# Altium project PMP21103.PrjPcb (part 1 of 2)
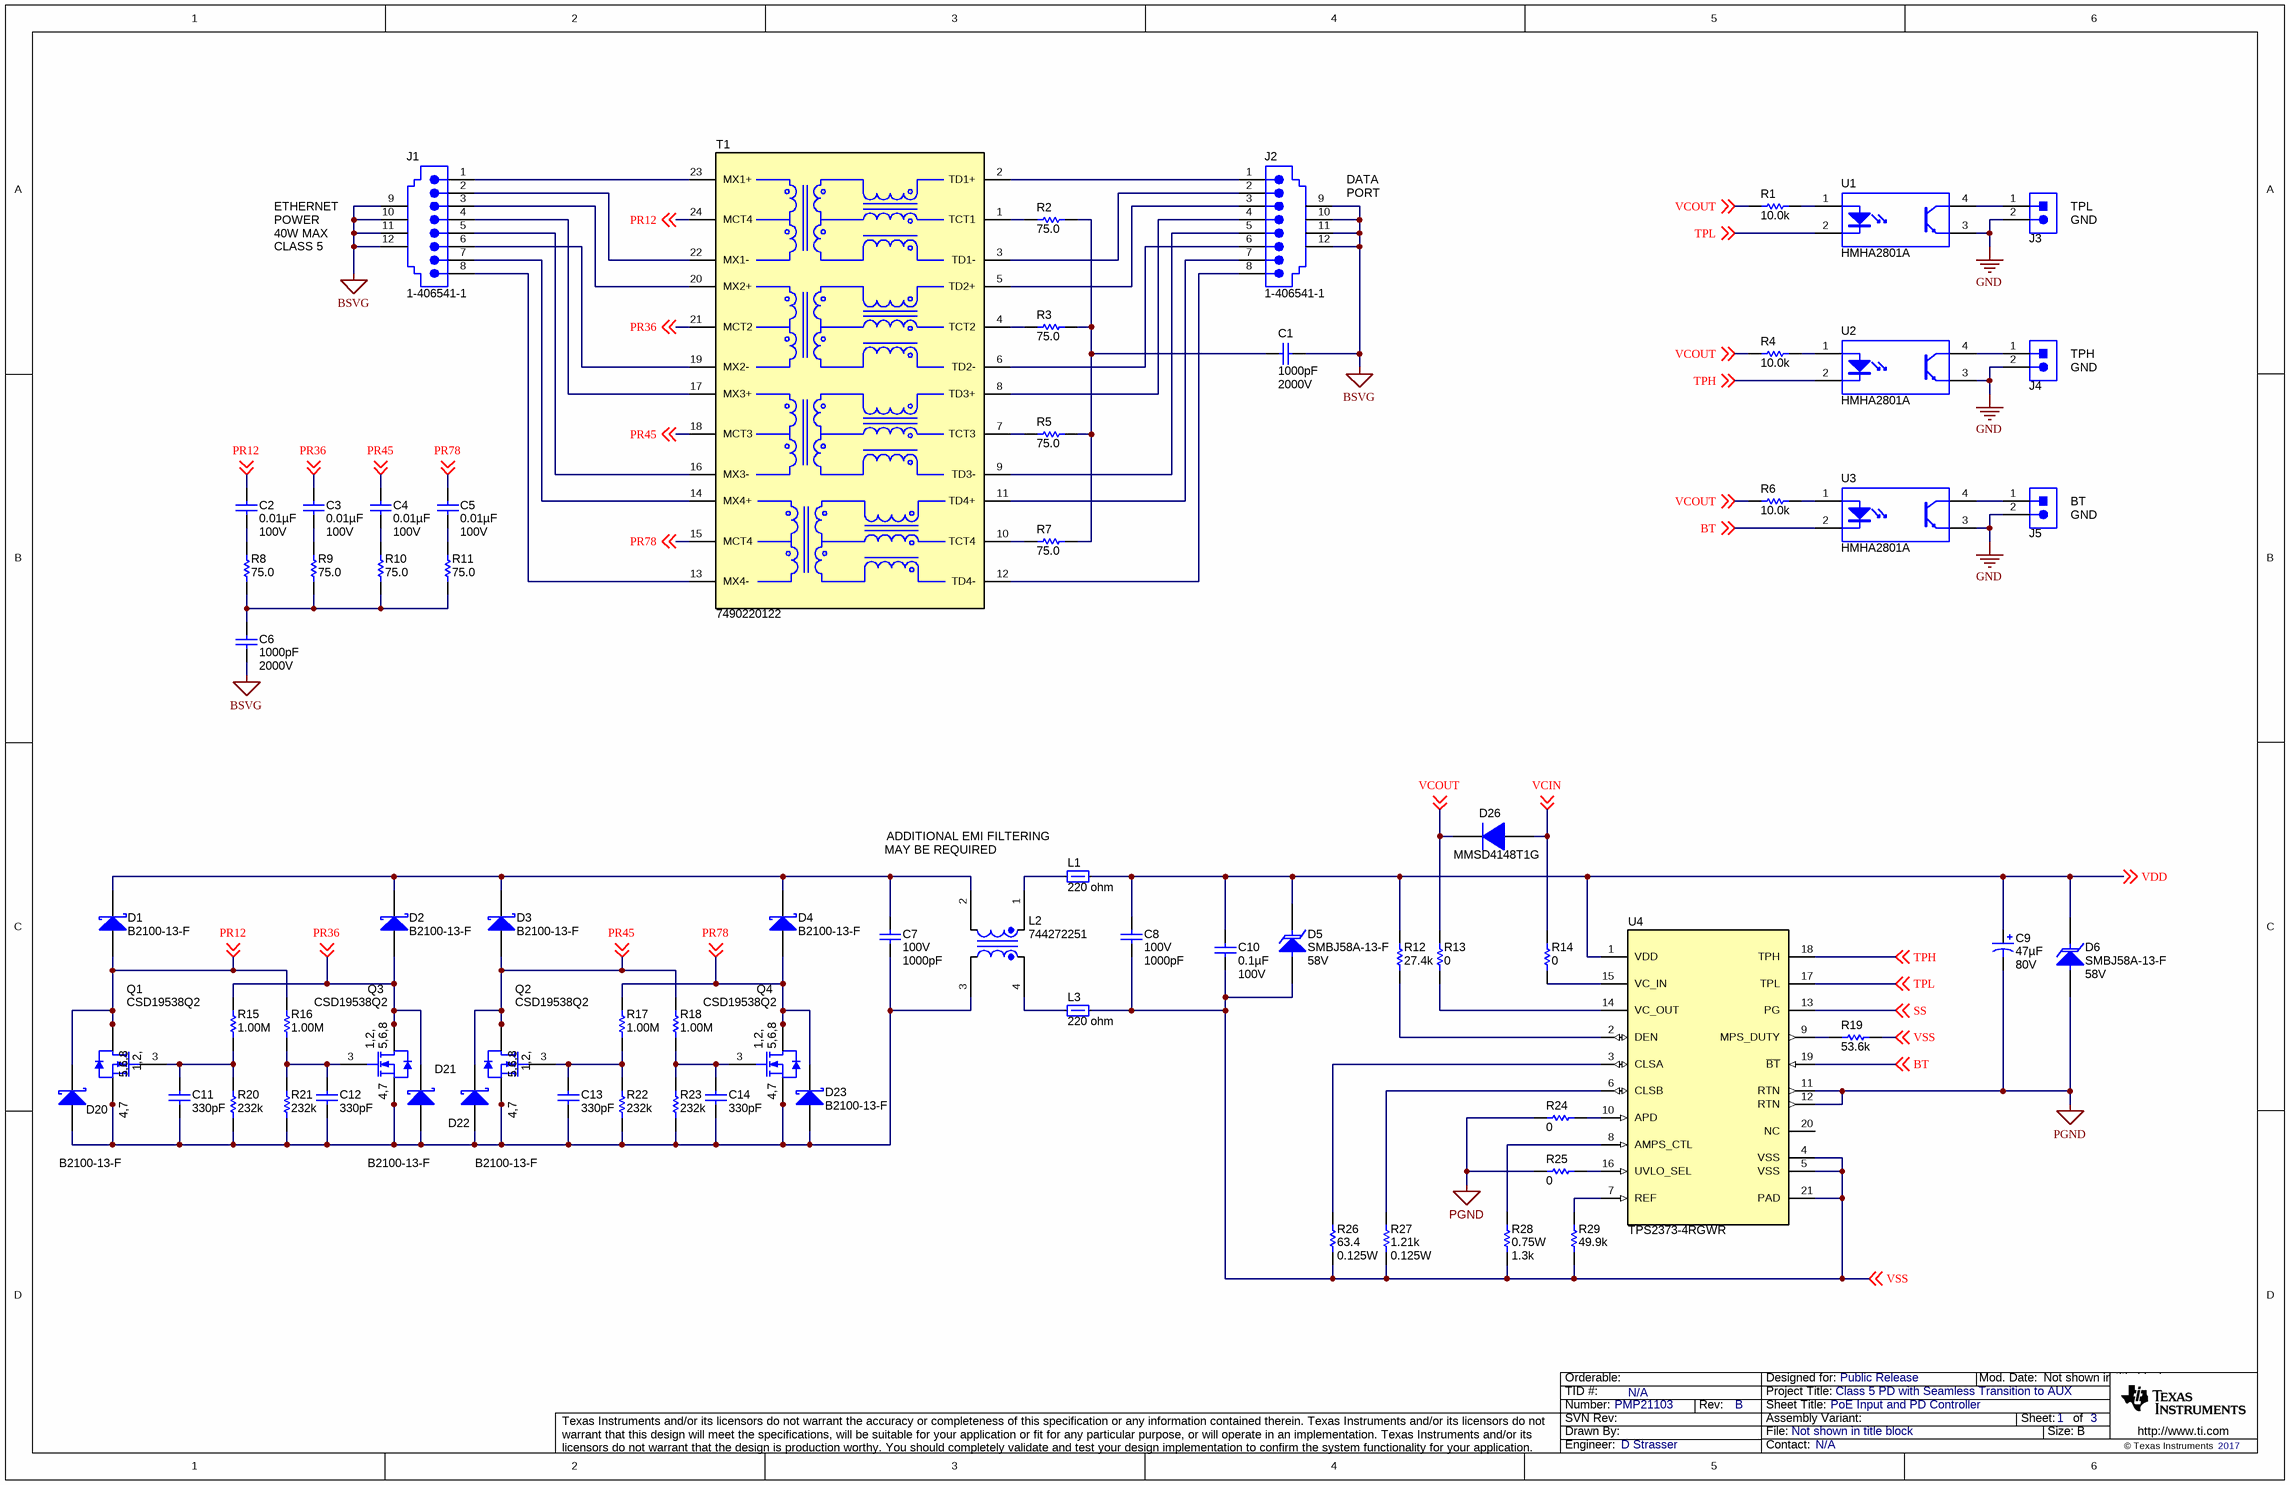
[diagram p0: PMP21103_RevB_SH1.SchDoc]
CopyrightYear: 2017; PCB_Layout: D Strasser; PCB_Rev: B; PRJ_Customer: Public Release; PRJ_Engineer: D Strasser; PRJ_Number: PMP21103; PRJ_Title: Class 5 PD with Seamless Transition to AUX; SCH_Rev: B; TechSupport: N/A; TID: N/A
3 sheets, 194 parts. Net scope: global (net labels, ports and power ports of the same name join across sheets).
Board file: PMP21103_RevB.PcbDoc
Sheets:
  PMP21103_RevB_SH1.SchDoc
  PMP21103_RevB_SH2.SchDoc
  PMP21103_RevB_SH3.SchDoc

## Sheet PMP21103_RevB_SH1.SchDoc: PoE Input and PD Controller
size 431 x 279 mm; Date: Not shown in title block; ApprovedBy: Not shown in title block; CheckedBy: Not shown in title block; Author: Not shown in title block; CompanyName: Not shown in title block; Engineer: Not shown in title block; Organization: Not shown in title block; Address1: Not shown in title block; Address2: Not shown in title block; Address3: Not shown in title block; Address4: Not shown in title block; DocumentNumber: 1; Revision: Use project parameter SCH_Rev; SheetNumber: 1; SheetTotal: 3; PageSetup: Record=PageOptions¦CenterHorizontal=True¦CenterVertical=True¦PrintScale=1.00¦XCorrection=1.00¦YCorrection=1.00¦PrintKind=0¦BorderSize=5000000¦LeftOffset=0¦BottomOffset=0¦Orientation=2¦PaperLength=1000¦PaperWidth=1000¦Scale=100¦PaperSource=15¦PrintQuality=600¦MediaType=1¦DitherType=10¦PaperKind=Letter¦PrintScaleMode=1

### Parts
C1  ValueDisplayed: 1000pF  Value2: 2000V  [1812]  (hidden comment: GR443QR73D102KW01L)
C2  ValueDisplayed: 0.01µF  Value2: 100V  [0603L]  (hidden comment: GRM188R72A103KA01D)
C3  ValueDisplayed: 0.01µF  Value2: 100V  [0603L]  (hidden comment: GRM188R72A103KA01D)
C4  ValueDisplayed: 0.01µF  Value2: 100V  [0603L]  (hidden comment: GRM188R72A103KA01D)
C5  ValueDisplayed: 0.01µF  Value2: 100V  [0603L]  (hidden comment: GRM188R72A103KA01D)
C6  ValueDisplayed: 1000pF  Value2: 2000V  [1812]  (hidden comment: GR443QR73D102KW01L)
C7  VDC_V: 100V  ValueDisplayed: 1000pF  [0603]  (hidden comment: GRM188R72A102KA01D)
C8  VDC_V: 100V  ValueDisplayed: 1000pF  [0603]  (hidden comment: GRM188R72A102KA01D)
C9  ValueDisplayed: 47µF  Value2: 80V  [SM_RADIAL_G]  (hidden comment: EEE-FK1K470P)
C10  ValueDisplayed: 0.1µF  Value2: 100V  [0805_HV]  (hidden comment: C2012X7R2A104K125AA)
C11  ValueDisplayed: 330pF  [0603L]  (hidden comment: GRM1885C1H331JA01D)
C12  ValueDisplayed: 330pF  [0603L]  (hidden comment: GRM1885C1H331JA01D)
C13  ValueDisplayed: 330pF  [0603L]  (hidden comment: GRM1885C1H331JA01D)
C14  ValueDisplayed: 330pF  [0603L]  (hidden comment: GRM1885C1H331JA01D)
D1  B2100-13-F  [SMB]
D2  B2100-13-F  [SMB]
D3  B2100-13-F  [SMB]
D4  B2100-13-F  [SMB]
D5  SMBJ58A-13-F  value 58V  [SMB]
D6  SMBJ58A-13-F  value 58V  [SMB]
D20  B2100-13-F  [SMB]
D21  B2100-13-F  [SMB]
D22  B2100-13-F  [SMB]
D23  B2100-13-F  [SMB]
D26  MMSD4148T1G  [SOD-123]
J1  1-406541-1  [TEC_1-406541-1]
J2  1-406541-1  [TEC_1-406541-1]
J3  PEC02SAAN  [CONN_PEC02SAAN]  (value not drawn)
J4  PEC02SAAN  [CONN_PEC02SAAN]  (value not drawn)
J5  PEC02SAAN  [CONN_PEC02SAAN]  (value not drawn)
L1  value 220 ohm  [0603]  (hidden comment: MPZ1608S221A)
L2  744272251  [WE-SL5]
L3  value 220 ohm  [0603]  (hidden comment: MPZ1608S221A)
Q1  CSD19538Q2  [DQK0006C]
Q2  CSD19538Q2  [DQK0006C]
Q3  CSD19538Q2  [DQK0006C]
Q4  CSD19538Q2  [DQK0006C]
R1  ValueDisplayed: 10.0k  [0603L]  (hidden comment: CRCW060310K0FKEA)
R2  value 75.0  [0603L]  (hidden comment: CRCW060375R0FKEA)
R3  value 75.0  [0603L]  (hidden comment: CRCW060375R0FKEA)
R4  ValueDisplayed: 10.0k  [0603L]  (hidden comment: CRCW060310K0FKEA)
R5  value 75.0  [0603L]  (hidden comment: CRCW060375R0FKEA)
R6  ValueDisplayed: 10.0k  [0603L]  (hidden comment: CRCW060310K0FKEA)
R7  value 75.0  [0603L]  (hidden comment: CRCW060375R0FKEA)
R8  value 75.0  [0603L]  (hidden comment: CRCW060375R0FKEA)
R9  value 75.0  [0603L]  (hidden comment: CRCW060375R0FKEA)
R10  value 75.0  [0603L]  (hidden comment: CRCW060375R0FKEA)
R11  value 75.0  [0603L]  (hidden comment: CRCW060375R0FKEA)
R12  ValueDisplayed: 27.4k  [0603L]  (hidden comment: CRCW060327K4FKEA)
R13  ValueDisplayed: 0  [0603L]  (hidden comment: CRCW06030000Z0EA)
R14  ValueDisplayed: 0  [0603L]  (hidden comment: CRCW06030000Z0EA)
R15  ValueDisplayed: 1.00M  [0603L]  (hidden comment: CRCW06031M00FKEA)
R16  ValueDisplayed: 1.00M  [0603L]  (hidden comment: CRCW06031M00FKEA)
R17  ValueDisplayed: 1.00M  [0603L]  (hidden comment: CRCW06031M00FKEA)
R18  ValueDisplayed: 1.00M  [0603L]  (hidden comment: CRCW06031M00FKEA)
R19  ValueDisplayed: 53.6k  [0603L]  (hidden comment: CRCW060353K6FKEA)
R20  ValueDisplayed: 232k  [0603L]  (hidden comment: CRCW0603232KFKEA)
R21  ValueDisplayed: 232k  [0603L]  (hidden comment: CRCW0603232KFKEA)
R22  ValueDisplayed: 232k  [0603L]  (hidden comment: CRCW0603232KFKEA)
R23  ValueDisplayed: 232k  [0603L]  (hidden comment: CRCW0603232KFKEA)
R24  ValueDisplayed: 0  [0603L]  (hidden comment: CRCW06030000Z0EA)
R25  ValueDisplayed: 0  [0603L]  (hidden comment: CRCW06030000Z0EA)
R26  ValueDisplayed: 63.4  Value2: 0.125W  [0805L]  (hidden comment: CRCW080563R4FKEA)
R27  ValueDisplayed: 1.21k  Value2: 0.125W  [0805L]  (hidden comment: CRCW08051K21FKEA)
R28  Value2: 0.75W  ValueDisplayed: 1.3k  [2010]  (hidden comment: CRCW20101K30JNEF)
R29  ValueDisplayed: 49.9k  [0603L]  (hidden comment: CRCW060349K9FKEA)
T1  7490220122  [Wurth_7490220122]
U1  HMHA2801A  [MFP04A]
U2  HMHA2801A  [MFP04A]
U3  HMHA2801A  [MFP04A]
U4  TPS2373-4RGWR  [RGW0020B]

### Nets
BSVG: C1.1 C6.2 J1.9 J1.10 J1.11 J1.12 J2.9 J2.10 J2.11 J2.12
GND: J3.2 J4.2 J5.2 U1.3(E) U2.3(E) U3.3(E)
PGND: C9.2(-) D6.2(A) R24.1 R25.2 U4.11(RTN) U4.12(RTN)
BT: U3.2(K) U4.19(~{BT}) ; off-sheet BT
PR12: C2.1 D1.2(A) D20.1(K) Q1.1(D) Q1.2(D) Q1.5(D) Q1.6(D) Q1.8(D) R16.1 T1.24(MCT4) ; off-sheet PR12
PR36: C3.1 D2.2(A) D21.1(K) Q3.1(D) Q3.2(D) Q3.5(D) Q3.6(D) Q3.8(D) R15.1 T1.21(MCT2) ; off-sheet PR36
PR45: C4.1 D3.2(A) D22.1(K) Q2.1(D) Q2.2(D) Q2.5(D) Q2.6(D) Q2.8(D) R18.1 T1.18(MCT3) ; off-sheet PR45
PR78: C5.1 D4.2(A) D23.1(K) Q4.1(D) Q4.2(D) Q4.5(D) Q4.6(D) Q4.8(D) R17.1 T1.15(MCT4) ; off-sheet PR78
SS: U4.13(PG) ; off-sheet SS
TPH: U2.2(K) U4.18(TPH) ; off-sheet TPH
TPL: U1.2(K) U4.17(TPL) ; off-sheet TPL
VCIN: D26.2(A) R14.2 ; off-sheet VCIN
VCOUT: D26.1(K) R1.1 R4.1 R6.1 R13.2 ; off-sheet VCOUT
VDD: C8.1 C9.1(+) C10.2 D5.1(K) D6.1(K) L1.2 R12.2 U4.1(VDD) ; off-sheet VDD
VSS: C8.2 C10.1 D5.2(A) L3.2 R19.2 R26.1 R27.1 R28.1 R29.1 U4.4(VSS) U4.5(VSS) U4.21(PAD) ; off-sheet VSS
NetC1_2: C1.2 R2.1 R3.1 R5.1 R7.1
NetC2_2: C2.2 R8.2
NetC3_2: C3.2 R9.2
NetC4_2: C4.2 R10.2
NetC5_2: C5.2 R11.2
NetC6_1: C6.1 R8.1 R9.1 R10.1 R11.1
NetC7_1: C7.1 D1.1(K) D2.1(K) D3.1(K) D4.1(K) L2.2
NetC7_2: C7.2 C11.2 C12.2 C13.2 C14.2 D20.2(A) D21.2(A) D22.2(A) D23.2(A) L2.3 Q1.4(S) Q1.7(S) Q2.4(S) Q2.7(S) Q3.4(S) Q3.7(S) Q4.4(S) Q4.7(S) R20.1 R21.1 R22.1 R23.1
NetC11_1: C11.1 Q1.3(G) R15.2 R20.2
NetC12_1: C12.1 Q3.3(G) R16.2 R21.2
NetC13_1: C13.1 Q2.3(G) R17.2 R22.2
NetC14_1: C14.1 Q4.3(G) R18.2 R23.2
NetJ1_1: J1.1 T1.23(MX1+)
NetJ1_2: J1.2 T1.22(MX1-)
NetJ1_3: J1.3 T1.20(MX2+)
NetJ1_4: J1.4 T1.17(MX3+)
NetJ1_5: J1.5 T1.16(MX3-)
NetJ1_6: J1.6 T1.19(MX2-)
NetJ1_7: J1.7 T1.14(MX4+)
NetJ1_8: J1.8 T1.13(MX4-)
NetJ2_1: J2.1 T1.2(TD1+)
NetJ2_2: J2.2 T1.3(TD1-)
NetJ2_3: J2.3 T1.5(TD2+)
NetJ2_4: J2.4 T1.8(TD3+)
NetJ2_5: J2.5 T1.9(TD3-)
NetJ2_6: J2.6 T1.6(TD2-)
NetJ2_7: J2.7 T1.11(TD4+)
NetJ2_8: J2.8 T1.12(TD4-)
NetJ3_1: J3.1 U1.4(C)
NetJ4_1: J4.1 U2.4(C)
NetJ5_1: J5.1 U3.4(C)
NetL1_1: L1.1 L2.1
NetL2_4: L2.4 L3.1
NetR1_2: R1.2 U1.1(A)
NetR2_2: R2.2 T1.1(TCT1)
NetR3_2: R3.2 T1.4(TCT2)
NetR4_2: R4.2 U2.1(A)
NetR5_2: R5.2 T1.7(TCT3)
NetR6_2: R6.2 U3.1(A)
NetR7_2: R7.2 T1.10(TCT4)
NetR12_1: R12.1 U4.2(DEN)
NetR13_1: R13.1 U4.14(VC_OUT)
NetR14_1: R14.1 U4.15(VC_IN)
NetR19_1: R19.1 U4.9(MPS_DUTY)
NetR24_2: R24.2 U4.10(APD)
NetR25_1: R25.1 U4.16(UVLO_SEL)
NetR26_2: R26.2 U4.3(CLSA)
NetR27_2: R27.2 U4.6(CLSB)
NetR28_2: R28.2 U4.8(AMPS_CTL)
NetR29_2: R29.2 U4.7(REF)

Not connected (* = marked no-connect by the designer): U4 20(NC)

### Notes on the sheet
- ETHERNET
- 40W MAX
- POWER
- (near J2) DATA
- (near J2) PORT
- (near J3) TPL
- (near J3) GND
- CLASS 5
- (near J4) TPH
- (near J4) GND
- (near J5) BT
- (near J5) GND
- (near L1) ADDITIONAL EMI FILTERING
- MAY BE REQUIRED

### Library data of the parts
C1 C6 = GR443QR73D102KW01L: CAP, CERM, 1000 pF, 2000 V, +/- 10%, X7R, 1812; Manufacturer: MuRata; Polarized: N; CompType: Capacitor; Value: 1000pF; U/M: EA; Cap_F: 0.000000001; Tolerance_%: 10; Value1: Unknown; VDC_V: 2000; TaMin_C: -55; TaMax_C: 125; SizeArea_mm2: 14.4; SizeAreaWB_mm2: 23.1; SizeX_mm: 4.5; SizeY_mm: 3.2; SizeZ_mm: 1.35; AEC Category: Q200
C2-C5 = GRM188R72A103KA01D: CAP, CERM, 0.01 µF, 100 V, +/- 10%, X7R, 0603; Manufacturer: MuRata; Polarized: N; CompType: Capacitor; Value: 0.01uF; U/M: EA; Cap_F: 0.00000001; Tolerance_%: 10; Value1: Unknown; VDC_V: 100; TaMin_C: -55; TaMax_C: 125; Cap_Case: 0603; SizeArea_mm2: 1.28; SizeAreaWB_mm2: 4.68; SizeX_mm: 1.6; SizeY_mm: 0.8; SizeZ_mm: 1; AEC Category: Q200
C7 C8 = CMP-0007467-2: CAP, CERM, 1000 pF, 100 V, +/- 10%, X7R, 0603; Manufacturer: MuRata; TaMin_C: -55°C; Polarized: N; SizeAreaWB_mm2: 4.68; Value1: Unknown; U/M: EA; Value: 1000pF; TaMax_C: 125°C; SizeZ_mm: 1; SizeX_mm: 1.6; SizeY_mm: 0.8; SizeArea_mm2: 1.28; Cap_F: 1nF; AEC Category: Q200
C9 = EEE-FK1K470P: CAP, AL, 47 µF, 80 V, +/- 20%, 0.7 ohm, AEC-Q200 Grade 2, SMD; Manufacturer: Panasonic; Polarized: Y; CompType: Capacitor; Value: 47uF; U/M: EA; Cap_F: 0.000047; Tolerance_%: 20; Value1: 0.7 ohm; VDC_V: 80; ESR_ohm: 0.7; IRMS_A: 0.2; TaMin_C: -55; TaMax_C: 105; Cap_Case: G; AEC Category: Q200; AEC Grade: 2; SizeAreaWB_mm2: 172.2; SizeArea_mm2: 123.6; SizeX_mm: 12; SizeY_mm: 10.3; SizeZ_mm: 10.2
C10 = C2012X7R2A104K125AA: CAP, CERM, 0.1 µF, 100 V, +/- 10%, X7R, 0805; Manufacturer: TDK; Polarized: N; CompType: Capacitor; Value: 0.1uF; U/M: EA; Cap_F: 0.0000001; Tolerance_%: 10; ESR_ohm: 0.020726; Value1: 0.020726 ohm; VDC_V: 100; IRMS_A: 1.456; TaMin_C: -55; TaMax_C: 125; Cap_Case: 0805; SizeArea_mm2: 2.5; SizeAreaWB_mm2: 6.75; SizeX_mm: 2; SizeY_mm: 1.25; SizeZ_mm: 1.45; AEC Category: Q200
C11-C14 = GRM1885C1H331JA01D: CAP, CERM, 330 pF, 50 V, +/- 5%, C0G/NP0, 0603; Manufacturer: MuRata; Polarized: N; CompType: Capacitor; Value: 330pF; U/M: EA; Cap_F: 0.00000000033; Tolerance_%: 5; Value1: Unknown; VDC_V: 50; Value2: 50V; TaMin_C: -55; TaMax_C: 125; Cap_Case: 0603; SizeArea_mm2: 1.28; SizeAreaWB_mm2: 4.68; SizeX_mm: 1.6; SizeY_mm: 0.8; SizeZ_mm: 1; AEC Category: Q200
D1-D4 = B2100-13-F: Diode, Schottky, 100V, 2A, SMB; Manufacturer: Diodes Inc.; U/M: EA; Vf_V: 0.79; Value2: 0.79V; Io_A: 2; Vr_V: 100; TJmax_C: 150; RJC_CperW: 15
D5 D6 = SMBJ58A-13-F: Diode, TVS, Uni, 58V, 600W, SMB; Manufacturer: Diodes Inc.; U/M: EA; Power_W: 5; Vr_V: 58; Value1: 5W
D20-D23 = CMP-0028397-2: Diode, Schottky, 100 V, 2 A, SMB; Manufacturer: Diodes Inc.; Value2: 0.79V; Value1: 2A; SizeArea_mm2: 21.336; Value: 100V; Green_REACh: Passed; Green_Lifecycle: Active; Vf_V: 790mV; SizeY_mm: 3.81; AEC Category: Q101; SizeZ_mm: 2.6; TJmax_C: 150°C; RJC_CperW: 15; SizeAreaWB_mm2: 44.156; SizeX_mm: 5.6
D26 = CMP-0029032-2: Diode, Switching, 100 V, 0.2 A, SOD-123; Manufacturer: ON Semiconductor; Value: 100V; SizeY_mm: 1.7; Io_A: 200mA; SizeAreaWB_mm2: 13.095; SizeArea_mm2: 6.545; Vf_V: 1V; TJmax_C: 150°C; SizeX_mm: 3.85; SizeZ_mm: 1.35; Value1: 0.2A; Green_Lifecycle: Active; AEC Category: Q101; Green_REACh: Passed
J1 J2 = 1-406541-1: RJ-45, Right Angle, No LED, tab up; Manufacturer: AMP; SymbolCreator: x0208326; CompType: Connector; U/M: EA; Note: updated F/S per request.  Made footprint to max size.  2103-11-27
J3-J5 = PEC02SAAN: Header, 100mil, 2x1, Tin, TH; Manufacturer: Sullins Connector Solutions; SymbolCreator: a0412235; U/M: EA
L1 L3 = MPZ1608S221A: Ferrite Bead, 220 ohm @ 100 MHz, 2.2 A, 0603; Manufacturer: TDK; Imax_A: 2.2; DCR_ohm: 0.05; Value1: 0.05 ohm; Value2: 2.2A; ZTyp@100MHz_Ohm: 220
L2 = 744272251: Coupled inductor, 250 µH,  A, 0.035 ohm, SMD; Manufacturer: Wurth Elektronik; SymbolCreator: a0412235; ValueDisplayed: 250µH; Value: 250uH; Ind_H: 250.0E-6; DCR_ohm: 0.035
Q1-Q4 = CSD19538Q2: MOSFET, N-CH, 100 V, 4.5 A, DQK0006C (WSON-6); Manufacturer: Texas Instruments; Alternate Manufacturer: None; U/M: EA; ChType: N; Value: 100V; VdsMax_V: 100; Value1: ? ohm; Value2: ? nC; Vgs_V: 20; IdsMax_A: 4.5; SizeAreaWB_mm2: 9; SizeArea_mm2: 4; SizeX_mm: 2; SizeZ_mm: 0.8; AEC Category: Q101
R1 R4 R6 = CRCW060310K0FKEA: RES, 10.0 k, 1%, 0.1 W, 0603; Manufacturer: Vishay-Dale; CompType: Resistor; Value: 10.0k; Res_ohm: 10000; Value_Code: 10k0; Tolerance_%: 1; Power_W: 0.1; Value2: 0.1W; VDC_V: 75; TempCo: 100 ppm/C; EIA_Code: E96; U/M: EA
R2 R3 R5 R7-R11 = CRCW060375R0FKEA: RES, 75.0 ohm, 1%, 0.1W, 0603; Manufacturer: Vishay-Dale; CompType: Resistor; Res_ohm: 75; Value_Code: 75R0; Tolerance_%: 1; Power_W: 0.1; TempCo: 100 ppm/C; EIA_Code: E96; U/M: EA
R12 = CRCW060327K4FKEA: RES, 27.4 k, 1%, 0.1 W, 0603; Manufacturer: Vishay-Dale; CompType: Resistor; Value: 27.4k; Res_ohm: 27400; Value_Code: 27k4; Tolerance_%: 1; Power_W: 0.1; Value2: 0.1W; VDC_V: 75; TempCo: 100 ppm/C; EIA_Code: E96; U/M: EA; SizeArea_mm2: 1.28; SizeX_mm: 1.6; SizeY_mm: 0.8; AEC Category: Q200; Green_Lifecycle: Active; Green_REACh: Passed
R13 R14 R24 R25 = CRCW06030000Z0EA: RES, 0, 5%, 0.1 W, 0603; Manufacturer: Vishay-Dale; CompType: Resistor; Value: 0; Value_Code: 0000; Tolerance_%: 5; Power_W: 0.1; Value2: 0.1W; VDC_V: 75; TempCo: 200 ppm/C; SizeArea_mm2: 1.28; SizeX_mm: 1.6; SizeY_mm: 0.8; SizeZ_mm: 1; EIA_Code: E24; U/M: EA; AEC Category: Q200
R15-R18 = CRCW06031M00FKEA: RES, 1.00 M, 1%, 0.1 W, 0603; Manufacturer: Vishay-Dale; CompType: Resistor; Value: 1.00Meg; Res_ohm: 1000000; Value_Code: 1M00; Tolerance_%: 1; Power_W: 0.1; Value2: 0.1W; VDC_V: 75; TempCo: 100 ppm/C; EIA_Code: E96; U/M: EA; SizeArea_mm2: 1.28; SizeX_mm: 1.6; SizeY_mm: 0.8; AEC Category: Q200
R19 = CRCW060353K6FKEA: RES, 53.6 k, 1%, 0.1 W, 0603; Manufacturer: Vishay-Dale; CompType: Resistor; Value: 53.6k; Res_ohm: 53600; Value_Code: 53k6; Tolerance_%: 1; Power_W: 0.1; Value2: 0.1W; VDC_V: 75; TempCo: 100 ppm/C; EIA_Code: E96; U/M: EA; AEC Category: Q200
R20-R23 = CRCW0603232KFKEA: RES, 232 k, 1%, 0.1 W, 0603; Manufacturer: Vishay-Dale; CompType: Resistor; Value: 232k; Res_ohm: 232000; Tolerance_%: 1; Power_W: 0.1; Value2: 0.1W; VDC_V: 75; TempCo: 100 ppm/C; EIA_Code: E96; U/M: EA; SizeArea_mm2: 1.28; SizeX_mm: 1.6; SizeY_mm: 0.8; AEC Category: Q200
R26 = CRCW080563R4FKEA: RES, 63.4, 1%, 0.125 W, 0805; Manufacturer: Vishay-Dale; CompType: Resistor; Value: 63.4; Value_Code: 63R4; Tolerance_%: 1; Power_W: 0.125; VDC_V: 150; TempCo: 100 ppm/C; EIA_Code: E96; U/M: EA
R27 = CRCW08051K21FKEA: RES, 1.21 k, 1%, 0.125 W, 0805; Manufacturer: Vishay-Dale; CompType: Resistor; Value: 1.21k; Res_ohm: 1210; Value_Code: 1k21; Tolerance_%: 1; Power_W: 0.125; VDC_V: 150; TempCo: 100 ppm/C; EIA_Code: E96; U/M: EA; SizeArea_mm2: 2.5; SizeX_mm: 2; SizeY_mm: 1.25; SizeZ_mm: 1.45; AEC Category: Q200
R28 = CMP-0016077-3: RES, 1.3 k, 5%, 0.75 W, AEC-Q200 Grade 0, 2010; Manufacturer: Vishay-Dale; Power_W: 750mW; TempCo: 200 ppm/C; Value_Code: 1k30; Value: 1.3k; EIA_Code: E24; SizeX_mm: 5; SizeY_mm: 2.5; SizeZ_mm: 1.66; SizeArea_mm2: 12.5; CompType: Resistor; AEC Qualified: Y; VDC_V: 400V; AEC Grade: 0; AEC Category: Q200
R29 = CRCW060349K9FKEA: RES, 49.9 k, 1%, 0.1 W, 0603; Manufacturer: Vishay-Dale; CompType: Resistor; Value: 49.9k; Res_ohm: 49900; Value_Code: 49k9; Tolerance_%: 1; Power_W: 0.1; Value2: 0.1W; VDC_V: 75; TempCo: 100 ppm/C; EIA_Code: E96; U/M: EA; AEC Category: Q200
T1 = 7490220122: Transformer, 350 uH, SMT; Manufacturer: Wurth Elektronik; SymbolCreator: Altium; ValueDisplayed: 350µH; Value: 350uH; Lp: 350
U1-U3 = HMHA2801A: Optocoupler, 3.75 kV, 80-160% CTR, SMT; Manufacturer: Fairchild Semiconductor; CTR (Min): 80%; CTR (Max): 160%; Voltage_Isolation_Vrms: 3750V; SizeAreaWB_mm2: 4; SizeArea_mm2: 1
U4 = TPS2373-4RGWR: High-Power PoE PD Interface with Advanced Startup, RGW0020B (VQFN-20); Alternate PartNumber: TPS2373-4RGWT; Manufacturer: Texas Instruments; SymbolCreator: Altium; SizeArea_mm2: 25; SizeAreaWB_mm2: 49; SizeX_mm: 5; SizeZ_mm: 1; CompType: IC; U/M: EA

## Sheet PMP21103_RevB_SH2.SchDoc: Active Clamp Forward Converter
size 431 x 279 mm; Date: Not shown in title block; ApprovedBy: Not shown in title block; CheckedBy: Not shown in title block; Author: Not shown in title block; CompanyName: Not shown in title block; Engineer: Not shown in title block; Organization: Not shown in title block; Address1: Not shown in title block; Address2: Not shown in title block; Address3: Not shown in title block; Address4: Not shown in title block; DocumentNumber: 2; Revision: Use project parameter SCH_Rev; SheetNumber: 2; SheetTotal: 3; PageSetup: Record=PageOptions¦CenterHorizontal=True¦CenterVertical=True¦PrintScale=1.00¦XCorrection=1.00¦YCorrection=1.00¦PrintKind=0¦BorderSize=5000000¦LeftOffset=0¦BottomOffset=0¦Orientation=2¦PaperLength=1000¦PaperWidth=1000¦Scale=100¦PaperSource=15¦PrintQuality=600¦MediaType=1¦DitherType=10¦PaperKind=Letter¦PrintScaleMode=1
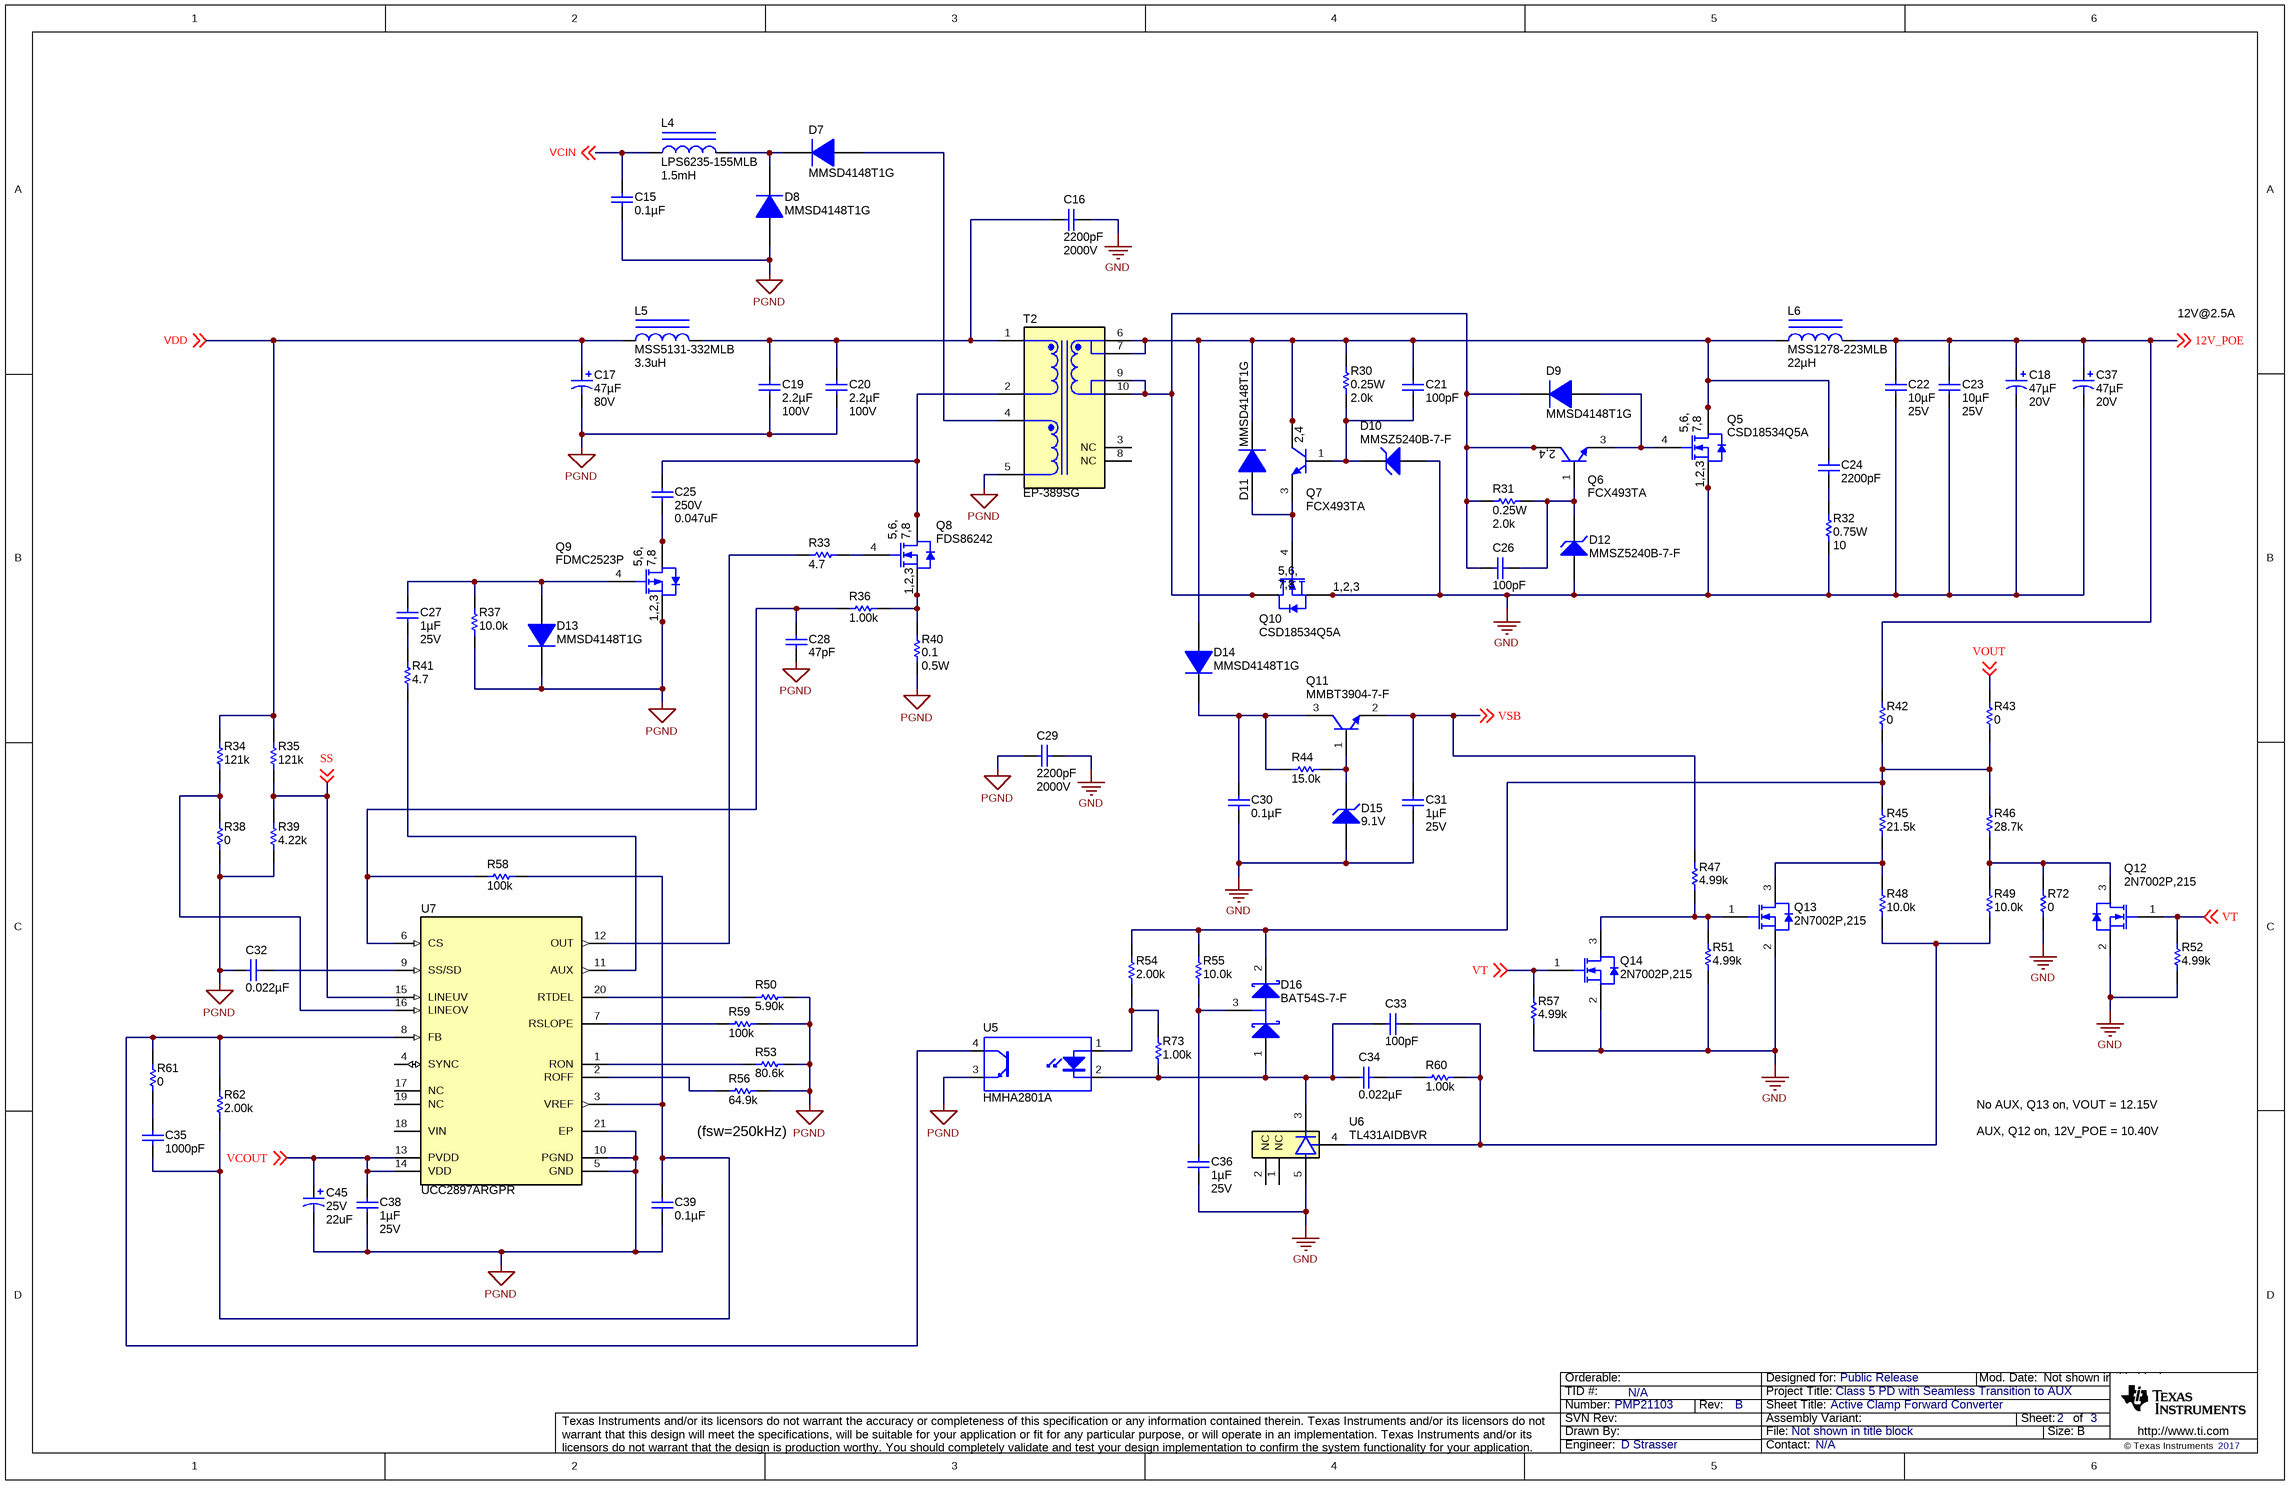
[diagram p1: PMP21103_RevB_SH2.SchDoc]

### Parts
C15  ValueDisplayed: 0.1µF  [0603]  (hidden comment: C1608X7R1H104K080AA)
C16  ValueDisplayed: 2200pF  Value2: 2000V  [1812]  (hidden comment: C4532X7R3D222K130KA)
C17  ValueDisplayed: 47µF  Value2: 80V  [SM_RADIAL_G]  (hidden comment: EEE-FK1K470P)
C18  ValueDisplayed: 47µF  Value2: 20V  [SM_RADIAL_8MM]  (hidden comment: 20SVP47M)
C19  ValueDisplayed: 2.2µF  Value2: 100V  [1210_270]  (hidden comment: GRM32ER72A225KA35L)
C20  ValueDisplayed: 2.2µF  Value2: 100V  [1210_270]  (hidden comment: GRM32ER72A225KA35L)
C21  ValueDisplayed: 100pF  [0603L]  (hidden comment: C1608C0G1H101J080AE)
C22  ValueDisplayed: 10µF  Value2: 25V  [1210_220]  (hidden comment: 885012209028)
C23  ValueDisplayed: 10µF  Value2: 25V  [1210_220]  (hidden comment: 885012209028)
C24  ValueDisplayed: 2200pF  [0603L]  (hidden comment: GRM188R71H222KA01D)
C25  VDC_V: 250V  ValueDisplayed: 0.047uF  [1206_180]  (hidden comment: GRM31CR72E473KW03L)
C26  ValueDisplayed: 100pF  [0603L]  (hidden comment: C1608C0G1H101J080AE)
C27  ValueDisplayed: 1µF  Value2: 25V  [0805L]  (hidden comment: GRM21BR71E105KA99L)
C28  ValueDisplayed: 47pF  [0603L]  (hidden comment: GRM1885C1H470JA01D)
C29  ValueDisplayed: 2200pF  Value2: 2000V  [1812]  (hidden comment: C4532X7R3D222K130KA)
C30  ValueDisplayed: 0.1µF  [0603L]  (hidden comment: C1608X7R1H104K080AA)
C31  ValueDisplayed: 1µF  Value2: 25V  [0805_HV]  (hidden comment: GRM21BR71E105KA99L)
C32  ValueDisplayed: 0.022µF  [0603L]  (hidden comment: GRM188R71H223KA01D)
C33  ValueDisplayed: 100pF  [0603L]  (hidden comment: C1608C0G1H101J080AE)
C34  ValueDisplayed: 0.022µF  [0603L]  (hidden comment: GRM188R71H223KA01D)
C35  ValueDisplayed: 1000pF  [0603]  (hidden comment: GRM188R71H102KA01D)
C36  ValueDisplayed: 1µF  Value2: 25V  [0805_HV]  (hidden comment: GRM21BR71E105KA99L)
C37  ValueDisplayed: 47µF  Value2: 20V  [SM_RADIAL_8MM]  (hidden comment: 20SVP47M)
C38  ValueDisplayed: 1µF  Value2: 25V  [0805L]  (hidden comment: GRM21BR71E105KA99L)
C39  ValueDisplayed: 0.1µF  [0603L]  (hidden comment: C1608X7R1H104K080AA)
C45  VDC_V: 25V  ValueDisplayed: 22uF  [SM_RADIAL_C]  (hidden comment: EEE-FK1E220R)
D7  MMSD4148T1G  [SOD-123]
D8  MMSD4148T1G  [SOD-123]
D9  MMSD4148T1G  [SOD-123]
D10  MMSZ5240B-7-F  [SOD-123]
D11  MMSD4148T1G  [SOD-123]
D12  MMSZ5240B-7-F  [SOD-123]
D13  MMSD4148T1G  [SOD-123]
D14  MMSD4148T1G  [SOD-123]
D15  value 9.1V  [SOD-523]  (hidden comment: BZT52C9V1T-7)
D16  BAT54S-7-F  [SOT-23]
L4  LPS6235-155MLB  ValueDisplayed: 1.5mH  [LPS6235]
L5  MSS5131-332MLB  value 3.3uH  [MSS5131]
L6  MSS1278-223MLB  ValueDisplayed: 22µH  [MSS1278]
Q5  CSD18534Q5A  [DQJ0008A]
Q6  FCX493TA  [SOT-89-3]
Q7  FCX493TA  [SOT-89-3]
Q8  FDS86242  [SOIC-8]
Q9  FDMC2523P  [MLP08S]
Q10  CSD18534Q5A  [DQJ0008A]
Q11  MMBT3904-7-F  [SOT-23]
Q12  2N7002P,215  [SOT-23]
Q13  2N7002P,215  [SOT-23]
Q14  2N7002P,215  [SOT-23]
R30  Value2: 0.25W  ValueDisplayed: 2.0k  [1206L]  (hidden comment: CRCW12062K00JNEA)
R31  Value2: 0.25W  ValueDisplayed: 2.0k  [1206L]  (hidden comment: CRCW12062K00JNEA)
R32  Value2: 0.75W  ValueDisplayed: 10  [2010L]  (hidden comment: CRCW201010R0JNEF)
R33  ValueDisplayed: 4.7  [0603L]  (hidden comment: CRCW06034R70JNEA)
R34  ValueDisplayed: 121k  [0603L]  (hidden comment: CRCW0603121KFKEA)
R35  ValueDisplayed: 121k  [0603L]  (hidden comment: CRCW0603121KFKEA)
R36  ValueDisplayed: 1.00k  [0603]  (hidden comment: CRCW06031K00FKEA)
R37  ValueDisplayed: 10.0k  [0603L]  (hidden comment: CRCW060310K0FKEA)
R38  ValueDisplayed: 0  [0603L]  (hidden comment: CRCW06030000Z0EA)
R39  ValueDisplayed: 4.22k  [0603L]  (hidden comment: CRCW06034K22FKEA)
R40  value 0.1  Value2: 0.5W  [2010L]  (hidden comment: ERJ-L1DKF10CU)
R41  ValueDisplayed: 4.7  [0603L]  (hidden comment: CRCW06034R70JNEA)
R42  ValueDisplayed: 0  [0603L]  (hidden comment: CRCW06030000Z0EA)
R43  ValueDisplayed: 0  [0603L]  (hidden comment: CRCW06030000Z0EA)
R44  ValueDisplayed: 15.0k  [0603]  (hidden comment: CRCW060315K0FKEA)
R45  ValueDisplayed: 21.5k  [0603]  (hidden comment: CRCW060321K5FKEA)
R46  ValueDisplayed: 28.7k  [0603L]  (hidden comment: CRCW060328K7FKEA)
R47  ValueDisplayed: 4.99k  [0603L]  (hidden comment: CRCW06034K99FKEA)
R48  ValueDisplayed: 10.0k  [0603L]  (hidden comment: CRCW060310K0FKEA)
R49  ValueDisplayed: 10.0k  [0603L]  (hidden comment: CRCW060310K0FKEA)
R50  ValueDisplayed: 5.90k  [0603L]  (hidden comment: CRCW06035K90FKEA)
R51  ValueDisplayed: 4.99k  [0603L]  (hidden comment: CRCW06034K99FKEA)
R52  ValueDisplayed: 4.99k  [0603L]  (hidden comment: CRCW06034K99FKEA)
R53  ValueDisplayed: 80.6k  [0603]  (hidden comment: CRCW060380K6FKEA)
R54  ValueDisplayed: 2.00k  [0603L]  (hidden comment: CRCW06032K00FKEA)
R55  ValueDisplayed: 10.0k  [0603L]  (hidden comment: CRCW060310K0FKEA)
R56  ValueDisplayed: 64.9k  [0603]  (hidden comment: CRCW060364K9FKEA)
R57  ValueDisplayed: 4.99k  [0603L]  (hidden comment: CRCW06034K99FKEA)
R58  ValueDisplayed: 100k  [0603L]  (hidden comment: CRCW0603100KFKEA)
R59  ValueDisplayed: 100k  [0603]  (hidden comment: CRCW0603100KFKEA)
R60  ValueDisplayed: 1.00k  [0603L]  (hidden comment: CRCW06031K00FKEA)
R61  ValueDisplayed: 0  [0603L]  (hidden comment: CRCW06030000Z0EA)
R62  ValueDisplayed: 2.00k  [0603L]  (hidden comment: CRCW06032K00FKEA)
R72  ValueDisplayed: 0  [0603L]  (hidden comment: CRCW06030000Z0EA)
R73  ValueDisplayed: 1.00k  [0603L]  (hidden comment: CRCW06031K00FKEA)
T2  EP-389SG  [Mentech_EP-389SG]
U5  HMHA2801A  [MFP04A]
U6  TL431AIDBVR  [DBV0005A_N]
U7  UCC2897ARGPR  [RGP0020D]

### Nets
GND: C16.1 C18.2(-) C22.2 C23.2 C29.1 C30.1 C31.2 C36.2 C37.2(-) D10.2(A) D12.2(A) D15.2(A) Q5.1(S) Q5.2(S) Q5.3(S) Q10.1(S) Q10.2(S) Q10.3(S) Q12.2(S) Q13.2(S) Q14.2(S) R32.1 R51.1 R52.1 R57.1 R72.1 U6.5(A)
PGND: C15.1 C17.2(-) C19.2 C20.2 C28.2 C29.2 C32.2 C38.2 C39.1 C45.2(-) D8.2(A) D13.1(K) Q9.1(S) Q9.2(S) Q9.3(S) R37.1 R38.1 R39.1 R40.1 R50.1 R53.2 R56.2 R59.2 T2.5 U5.3(E) U7.5(GND) U7.10(PGND) U7.21(EP)
12V_POE: C18.1(+) C22.1 C23.1 C37.1(+) L6.2 R42.2 ; off-sheet 12V_POE
SS: R35.1 R39.2 U7.15(LINEUV) ; off-sheet SS
VCIN: C15.2 L4.1 ; off-sheet VCIN
VCOUT: C38.1 C45.1(+) U7.13(PVDD) U7.14(VDD) ; off-sheet VCOUT
VDD: C17.1(+) L5.1 R34.2 R35.2 ; off-sheet VDD
VOUT: R43.2 ; off-sheet VOUT
VSB: C31.1 Q11.2(E) R47.2 ; off-sheet VSB
VT: Q12.1(G) Q14.1(G) R52.2 R57.2 ; off-sheet VT
NetC16_2: C16.2 C19.1 C20.1 L5.2 T2.1
NetC21_1: C21.1 D10.1(K) Q7.1(B) R30.1
NetC21_2: C21.2 C24.1 D11.1(K) D14.2(A) L6.1 Q5.5(D) Q5.6(D) Q5.7(D) Q5.8(D) Q5.9(D) Q7.2(C) Q7.4(C) R30.2 T2.6 T2.7
NetC24_2: C24.2 R32.2
NetC25_1: C25.1 Q8.5(D) Q8.6(D) Q8.7(D) Q8.8(D) T2.2
NetC25_2: C25.2 Q9.5(D) Q9.6(D) Q9.7(D) Q9.8(D)
NetC26_1: C26.1 D9.1(K) Q6.2(C) Q6.4(C) Q10.5(D) Q10.6(D) Q10.7(D) Q10.8(D) Q10.9(D) R31.1 T2.9 T2.10
NetC26_2: C26.2 D12.1(K) Q6.1(B) R31.2
NetC27_1: C27.1 D13.2(A) Q9.4(G) R37.2
NetC27_2: C27.2 R41.2
NetC28_1: C28.1 R36.1 R58.1 U7.6(CS)
NetC30_2: C30.2 D14.1(K) Q11.3(C) R44.2
NetC32_1: C32.1 U7.9(SS/SD)
NetC33_1: C33.1 R48.1 R49.1 R60.1 U6.4(REF)
NetC33_2: C33.2 C34.2 D16.1(A) R73.2 U5.2(K) U6.3(C)
NetC34_1: C34.1 R60.2
NetC35_1: C35.1 R61.1
NetC35_2: C35.2 C39.2 R58.2 R62.2 U7.3(VREF)
NetC36_1: C36.1 D16.3(C) R55.1
NetD7_1: D7.1(K) D8.1(K) L4.2
NetD7_2: D7.2(A) T2.4
NetD9_2: D9.2(A) Q5.4(G) Q6.3(E)
NetD11_2: D11.2(A) Q7.3(E) Q10.4(G)
NetD15_1: D15.1(K) Q11.1(B) R44.1
NetD16_2: D16.2(K) R42.1 R43.1 R45.2 R46.2 R54.1 R55.2
NetQ8_1: Q8.1(S) Q8.2(S) Q8.3(S) R36.2 R40.2
NetQ8_4: Q8.4(G) R33.2
NetQ12_3: Q12.3(D) R46.1 R49.2 R72.2
NetQ13_1: Q13.1(G) Q14.3(D) R47.1 R51.2
NetQ13_3: Q13.3(D) R45.1 R48.2
NetR33_1: R33.1 U7.12(OUT)
NetR34_1: R34.1 R38.2 U7.16(LINEOV)
NetR41_1: R41.1 U7.11(AUX)
NetR50_2: R50.2 U7.20(RTDEL)
NetR53_1: R53.1 U7.1(RON)
NetR54_2: R54.2 R73.1 U5.1(A)
NetR56_1: R56.1 U7.2(ROFF)
NetR59_1: R59.1 U7.7(RSLOPE)
NetR61_2: R61.2 R62.1 U5.4(C) U7.8(FB)

Not connected (* = marked no-connect by the designer): T2 3(NC) 8(NC); U6 1(NC) 2(NC); U7 4(SYNC) 17(NC) 18(VIN) 19(NC)

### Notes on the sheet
- 12V@2.5A
- No AUX, Q13 on, VOUT = 12.15V
- (near R56) (fsw=250kHz)
- AUX, Q12 on, 12V_POE = 10.40V

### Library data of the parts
C15 = C1608X7R1H104K080AA: CAP, CERM, 0.1 µF, 50 V, +/- 10%, X7R, 0603; Manufacturer: TDK; Polarized: N; CompType: Capacitor; Value: 0.1uF; U/M: EA; Cap_F: 0.0000001; Tolerance_%: 10; ESR_ohm: 0.0296; Value1: 0.0296 ohm; VDC_V: 50; Value2: 50V; IRMS_A: 0.97199; TaMin_C: -55; TaMax_C: 125; SizeArea_mm2: 1.28; SizeAreaWB_mm2: 4.68; SizeX_mm: 1.6; SizeY_mm: 0.8; SizeZ_mm: 1; AEC Category: Q200
C16 C29 = C4532X7R3D222K130KA: CAP, CERM, 2200 pF, 2000 V,+/- 10%, X7R, 1812; Manufacturer: TDK; Polarized: N; CompType: Capacitor; Value: 2200pF; U/M: EA; Cap_F: 0.0000000022; Tolerance_%: 10; VDC_V: 2000; TaMin_C: -55; TaMax_C: 125; SizeArea_mm2: 14.4; SizeAreaWB_mm2: 23.1; SizeX_mm: 4.5; SizeY_mm: 3.2; SizeZ_mm: 1.35; AEC Category: Q200; Green_Lifecycle: Active; Green_REACh: Passed
C17 = EEE-FK1K470P: as C9 on sheet PMP21103_RevB_SH1
C18 C37 = 20SVP47M: CAP, Aluminum Polymer, 47 µF, 20 V,+/- 20%, 0.045 ohm, 8x10 SMD; Manufacturer: Panasonic; Polarized: Y; CompType: Capacitor; Value: 47uF; U/M: EA; Cap_F: 0.000047; Tolerance_%: 20; ESR_ohm: 0.045; IRMS_A: 1.89; TaMin_C: -55; TaMax_C: 105; Cap_Case: 8.3x8.3x6.9; SizeAreaWB_mm2: 113.3; SizeArea_mm2: 74.7; SizeX_mm: 9; SizeY_mm: 8.3; SizeZ_mm: 10.2; AEC Category: Q200; Green_Lifecycle: Not Set; Green_REACh: Incomplete
C19 C20 = GRM32ER72A225KA35L: CAP, CERM, 2.2 µF, 100 V, +/- 10%, X7R, 1210; Manufacturer: MuRata; Polarized: N; CompType: Capacitor; Value: 2.2uF; U/M: EA; Cap_F: 0.0000022; Tolerance_%: 10; ESR_ohm: 0.007; Value1: 0.007 ohm; VDC_V: 100; IRMS_A: 4.4; TaMin_C: -55; TaMax_C: 125; Cap_Case: 1210; SizeArea_mm2: 8; SizeAreaWB_mm2: 14.7; SizeX_mm: 3.2; SizeY_mm: 2.5; SizeZ_mm: 2.7; AEC Category: Q200
C21 C26 C33 = C1608C0G1H101J080AE: CAP, CERM, 100 pF, 50 V,+/- 5%, C0G/NP0, 0603; Manufacturer: TDK; Polarized: N; CompType: Capacitor; Value: 100pF; U/M: EA; Cap_F: 0.0000000001; Tolerance_%: 5; VDC_V: 50; Value2: 50V; TaMin_C: -55; TaMax_C: 125; Cap_Case: 0603; SizeArea_mm2: 1.28; SizeAreaWB_mm2: 4.68; SizeX_mm: 1.6; SizeY_mm: 0.8; SizeZ_mm: 1; AEC Category: Q200; Green_Lifecycle: Active; Green_REACh: Passed
C22 C23 = 885012209028: CAP, CERM, 10 µF, 25 V,+/- 10%, X7R, 1210; Manufacturer: Wurth Elektronik; Polarized: N; CompType: Capacitor; Value: 10uF; U/M: EA; Cap_F: 0.00001; Tolerance_%: 10; VDC_V: 25; TaMin_C: -55; TaMax_C: 125; Cap_Case: 1210; SizeArea_mm2: 8; SizeAreaWB_mm2: 14.7; SizeX_mm: 3.2; SizeY_mm: 2.5; SizeZ_mm: 2.2; AEC Category: Q200
C24 = GRM188R71H222KA01D: CAP, CERM, 2200 pF, 50 V, +/- 10%, X7R, 0603; Manufacturer: MuRata; Polarized: N; CompType: Capacitor; Value: 2200pF; U/M: EA; Cap_F: 0.0000000022; Tolerance_%: 10; Value1: Unknown; VDC_V: 50; Value2: 50V; TaMin_C: -55; TaMax_C: 125; Cap_Case: 0603; SizeArea_mm2: 1.28; SizeAreaWB_mm2: 4.68; SizeX_mm: 1.6; SizeY_mm: 0.8; SizeZ_mm: 1; AEC Category: Q200
C25 = CMP-0008975-2: CAP, CERM, 0.047 uF, 250 V, +/- 10%, X7R, 1206; Manufacturer: MuRata; TaMin_C: -55°C; Polarized: N; SizeAreaWB_mm2: 10.92; Value1: Unknown; U/M: EA; TaMax_C: 125°C; SizeZ_mm: 1.8; SizeX_mm: 3.2; SizeY_mm: 1.6; Cap_Case: 1206; SizeArea_mm2: 5.12; Cap_F: 47nF; AEC Category: Q200
C27 C31 C36 C38 = GRM21BR71E105KA99L: CAP, CERM, 1 µF, 25 V, +/- 10%, X7R, 0805; Manufacturer: MuRata; Polarized: N; CompType: Capacitor; Value: 1uF; U/M: EA; Cap_F: 0.000001; Tolerance_%: 10; Value1: Unknown; VDC_V: 25; TaMin_C: -55; TaMax_C: 125; Cap_Case: 0805; SizeArea_mm2: 2.5; SizeAreaWB_mm2: 6.75; SizeX_mm: 2; SizeY_mm: 1.25; SizeZ_mm: 1.45; AEC Category: Q200
C28 = GRM1885C1H470JA01D: CAP, CERM, 47 pF, 50 V, +/- 5%, C0G/NP0, 0603; Manufacturer: MuRata; Polarized: N; CompType: Capacitor; Value: 47pF; U/M: EA; Cap_F: 0.000000000047; Tolerance_%: 5; Value1: Unknown; VDC_V: 50; Value2: 50V; TaMin_C: -55; TaMax_C: 125; Cap_Case: 0603; SizeArea_mm2: 1.28; SizeAreaWB_mm2: 4.68; SizeX_mm: 1.6; SizeY_mm: 0.8; SizeZ_mm: 1; AEC Category: Q200
C30 C39 = C1608X7R1H104K080AA: CAP, CERM, 0.1 µF, 50 V, +/- 10%, X7R, 0603; Manufacturer: TDK; Polarized: N; CompType: Capacitor; Value: 0.1uF; U/M: EA; Cap_F: 0.0000001; Tolerance_%: 10; ESR_ohm: 0.0296; Value1: 0.0296 ohm; VDC_V: 50; Value2: 50V; IRMS_A: 0.97199; TaMin_C: -55; TaMax_C: 125; Cap_Case: 0603; SizeArea_mm2: 1.28; SizeAreaWB_mm2: 4.68; SizeX_mm: 1.6; SizeY_mm: 0.8; SizeZ_mm: 1; AEC Category: Q200
C32 C34 = GRM188R71H223KA01D: CAP, CERM, 0.022 µF, 50 V, +/- 10%, X7R, 0603; Manufacturer: MuRata; Polarized: N; CompType: Capacitor; Value: 0.022uF; U/M: EA; Cap_F: 0.000000022; Tolerance_%: 10; Value1: Unknown; VDC_V: 50; Value2: 50V; TaMin_C: -55; TaMax_C: 125; Cap_Case: 0603; SizeArea_mm2: 1.28; SizeAreaWB_mm2: 4.68; SizeX_mm: 1.6; SizeY_mm: 0.8; SizeZ_mm: 1; AEC Category: Q200
C35 = GRM188R71H102KA01D: CAP, CERM, 1000 pF, 50 V,+/- 10%, X7R, 0603; Manufacturer: MuRata; Polarized: N; CompType: Capacitor; Value: 1000pF; U/M: EA; Cap_F: 0.000000001; Tolerance_%: 10; VDC_V: 50; Value2: 50V; TaMin_C: -55; TaMax_C: 125; SizeArea_mm2: 1.28; SizeAreaWB_mm2: 4.68; SizeX_mm: 1.6; SizeY_mm: 0.8; SizeZ_mm: 1; AEC Category: Q200; Green_Lifecycle: Active; Green_REACh: Passed
C45 = CMP-0010713-1: CAP, AL, 22 uF, 25 V, +/- 20%, 0.7 ohm, AEC-Q200 Grade 2, SMD; Manufacturer: Panasonic; TaMin_C: -55°C; ESR_ohm: 7d; Polarized: Y; SizeAreaWB_mm2: 62.05; Value1: 0.7 ohm; U/M: EA; Value: 22uF; TaMax_C: 105°C; SizeZ_mm: 5.4; SizeX_mm: 6.5; SizeY_mm: 5.3; Cap_Case: C; SizeArea_mm2: 34.45; CompType: Capacitor; Cap_F: 22µF; IRMS_A: 1.6dA; AEC Grade: 2; AEC Category: Q200
D7-D9 D11 D13 D14 = MMSD4148T1G: Diode, Switching, 100 V, 0.2 A, SOD-123; Manufacturer: ON Semiconductor; Value: 100V; U/M: EA; Vf_V: 1; Value1: 0.2A; Value2: 1V; Io_A: 0.2; Vr_V: 100; TJmax_C: 150; SizeAreaWB_mm2: 13.095; SizeArea_mm2: 6.545; SizeX_mm: 3.85; SizeY_mm: 1.7; SizeZ_mm: 1.35; AEC Category: Q101
D10 D12 = MMSZ5240B-7-F: Diode, Zener, 10 V, 500 mW, SOD-123; Manufacturer: Diodes Inc.; Value: 10V; U/M: EA; Power_W: 0.5; Vz_V: 10; Value1: 0.5W; RJA_CperW: 350; SymbolCreator: a0412235; SizeAreaWB_mm2: 13.095; SizeArea_mm2: 6.545; SizeX_mm: 3.85; SizeY_mm: 1.7; SizeZ_mm: 1.35; AEC Category: Q101
D15 = BZT52C9V1T-7: Diode, Zener, 9.1 V, 300 mW, SOD-523; Manufacturer: Diodes Inc.; SymbolCreator: a0412235; U/M: EA; Power_W: 0.3; Vz_V: 9.1; Value1: 0.3W; RJA_CperW: 417; SizeAreaWB_mm2: 5.13; SizeArea_mm2: 1.53; SizeX_mm: 1.7; SizeY_mm: 0.9; SizeZ_mm: 0.65; AEC Category: Q101
D16 = BAT54S-7-F: Diode, Schottky, 30 V, 0.2 A, SOT-23; Manufacturer: Diodes Inc.; Value: 30V; U/M: EA; Vf_V: 0.65; Value1: 0.2A; Value2: 0.65V; Io_A: 0.2; Vr_V: 30; TJmax_C: 125; SizeAreaWB_mm2: 14; SizeArea_mm2: 7.5; SizeX_mm: 2.5; SizeY_mm: 3; SizeZ_mm: 1.1; AEC Category: Q101
L4 = LPS6235-155MLB: Inductor, Shielded Drum Core, Ferrite, 1.5 mH, 0.14 A, 4.6 ohm, SMD; Manufacturer: Coilcraft; Value: 1.5mH; Ind_H: 1.5E-3; Imax_A: 0.14; Irms: 0.26A @ 40C rise; Isat: 0.14A @ 30% inductance drop; DCR_ohm: 4.6; Value1: 4.6 ohm; Value2: 0.14A; SizeAreaWB_mm2: 64; SizeArea_mm2: 36; SizeX_mm: 6; SizeZ_mm: 3.5; AEC Category: Q200; Green_Lifecycle: Not Set; Green_REACh: Incomplete
L5 = MSS5131-332MLB: Inductor, Shielded Drum Core, Ferrite, 3.3 µH, 1.73 A, 0.03 ohm, SMD; Manufacturer: Coilcraft; Ind_H: 3.3E-6; ValueDisplayed: 3.3µH; Imax_A: 1.73; Irms: 2.9A @ 40C rise; Isat: 1.73A @ 30% inductance drop; DCR_ohm: 0.03; Value2: 1.73A; SizeAreaWB_mm2: 50.41; SizeArea_mm2: 26.01; SizeX_mm: 5.1; SizeZ_mm: 3.1; AEC Category: Q200
L6 = MSS1278-223MLB: Inductor, Shielded Drum Core, Ferrite, 22 µH, 4 A, 0.04 ohm, SMD; Manufacturer: Coilcraft; Value: 22uH; Ind_H: 22.0E-6; Imax_A: 4; Irms: 4A @ 40C rise; Isat: 7.24A @ 30% inductance drop; DCR_ohm: 0.04; Value2: 4A; SizeAreaWB_mm2: 204.49; SizeArea_mm2: 151.29; SizeX_mm: 12.3; SizeZ_mm: 8.05; AEC Category: Q200; Green_Lifecycle: Not Set; Green_REACh: Incomplete
Q5 Q10 = CSD18534Q5A: MOSFET, N-CH, 60 V, 50 A, DQJ0008A (VSONP-8); Manufacturer: Texas Instruments; Alternate Manufacturer: None; Value: 60V; U/M: EA; ChType: N; VdsMax_V: 60; Value1: 0.0098 ohm; Rdson45_ohm: 0.0098; Value2: 22 nC; QgTyp_nC: 22; Vgs_V: 2.3; IdsMax_A: 50; SizeAreaWB_mm2: 55.2; SizeArea_mm2: 29.4; SizeX_mm: 6; SizeY_mm: 4.9; SizeZ_mm: 1.1; AEC Category: Q101
Q6 Q7 = FCX493TA, Diodes Inc.: Transistor, NPN, 100 V, 1 A, SOT-89; CompType: BJT; PNP: 0; NPN: 1; Vceo_V: 100; Vcesat1_V: 0.6; Value: 100 V; Value1: 1 A; HfeMax: 300; TaMin_C: -65; TaMax_C: 150; U/M: EA; SymbolCreator: a0412235; SizeAreaWB_mm2: 28.05; SizeArea_mm2: 18.45; SizeX_mm: 4.1; SizeY_mm: 4.5; SizeZ_mm: 1.5; AEC Category: Q101; Green_Lifecycle: Active; Green_REACh: Passed
Q8 = FDS86242: MOSFET, N-CH, 150 V, 4.1 A, SOIC-8; Manufacturer: Fairchild Semiconductor; Alternate Manufacturer: None; Value: 150V; U/M: EA; ChType: N; VdsMax_V: 150; Value1: ? ohm; Value2: 8.9 nC; QgTyp_nC: 8.9; Vgs_V: 20; IdsMax_A: 4.1; SizeAreaWB_mm2: 55.131; SizeArea_mm2: 29.351; SizeX_mm: 5.99; SizeY_mm: 4.9; SizeZ_mm: 1.75; AEC Category: Q101
Q9 = FDMC2523P: MOSFET, P-CH, -150 V, -3 A, QFN-8; Manufacturer: Fairchild Semiconductor; Alternate Manufacturer: None; Value: -150V; U/M: EA; ChType: P; Value1: ? ohm; Value2: 6.2 nC; QgTyp_nC: 6.2; Vgs_V: -30; SizeAreaWB_mm2: 18.49; SizeArea_mm2: 10.89; SizeX_mm: 3.3; SizeZ_mm: 0.8; AEC Category: Q101; AEC Qualified: N
Q11 = MMBT3904-7-F, Diodes Inc.: Transistor, NPN, 40 V, 0.2 A, SOT-23; CompType: BJT; PNP: 0; NPN: 1; Vceo_V: 40; Vcesat1_V: 0.2; Value: 40 V; Value1: 0.2 A; HfeMax: 400; TaMin_C: -55; TaMax_C: 150; SizeAreaWB_mm2: 14; SizeArea_mm2: 7.5; SizeX_mm: 2.5; SizeY_mm: 3; SizeZ_mm: 1.1; U/M: EA; AEC Category: Q101
Q12-Q14 = 2N7002P,215: MOSFET, N-CH, 60 V, 0.36 A, SOT-23; Manufacturer: Nexperia; Alternate Manufacturer: None; U/M: EA; ChType: N; Value: 60V; VdsMax_V: 60; Value1: 2 ohm; Rdson45_ohm: 2; Value2: 0.6 nC; QgTyp_nC: 0.6; Vgs_V: 20; IdsMax_A: 0.36; SizeAreaWB_mm2: 14; SizeArea_mm2: 7.5; SizeX_mm: 2.5; SizeY_mm: 3; SizeZ_mm: 1.1; AEC Category: Q101
R30 R31 = CRCW12062K00JNEA: RES, 2.0 k, 5%, 0.25 W, 1206; Manufacturer: Vishay-Dale; CompType: Resistor; Value: 2.0k; Res_ohm: 2000; Value_Code: 2k00; Tolerance_%: 5; Power_W: 0.25; VDC_V: 200; TempCo: 200 ppm/C; EIA_Code: E24; U/M: EA; SizeArea_mm2: 5.12; SizeX_mm: 3.2; SizeY_mm: 1.6; SizeZ_mm: 1.35; AEC Category: Q200
R32 = CRCW201010R0JNEF: RES, 10, 5%, 0.75 W, AEC-Q200 Grade 0, 2010; Manufacturer: Vishay-Dale; CompType: Resistor; Value: 10; Value_Code: 10R0; Tolerance_%: 5; Power_W: 0.75; VDC_V: 400; TempCo: 200 ppm/C; EIA_Code: E24; U/M: EA; SizeArea_mm2: 12.5; SizeY_mm: 2.5; SizeZ_mm: 1.66; AEC Category: Q200; AEC Qualified: Y; AEC Grade: 0
R33 R41 = CRCW06034R70JNEA: RES, 4.7, 5%, 0.1 W, 0603; Manufacturer: Vishay-Dale; CompType: Resistor; Value: 4.7; Value_Code: 4R70; Tolerance_%: 5; Power_W: 0.1; Value2: 0.1W; VDC_V: 75; TempCo: 200 ppm/C; EIA_Code: E24; U/M: EA; SizeArea_mm2: 1.28; SizeX_mm: 1.6; SizeY_mm: 0.8; SizeZ_mm: 1; AEC Category: Q200
R34 R35 = CRCW0603121KFKEA: RES, 121 k, 1%, 0.1 W, 0603; Manufacturer: Vishay-Dale; CompType: Resistor; Value: 121k; Res_ohm: 121000; Tolerance_%: 1; Power_W: 0.1; Value2: 0.1W; VDC_V: 75; TempCo: 100 ppm/C; EIA_Code: E96; U/M: EA; SizeArea_mm2: 1.28; SizeX_mm: 1.6; SizeY_mm: 0.8; AEC Category: Q200; Green_Lifecycle: Active; Green_REACh: Passed
R36 = CRCW06031K00FKEA: RES, 1.00 k, 1%, 0.1 W, 0603; Manufacturer: Vishay-Dale; CompType: Resistor; Value: 1.00k; Res_ohm: 1000; Value_Code: 1k00; Tolerance_%: 1; Power_W: 0.1; Value2: 0.1W; VDC_V: 75; TempCo: 100 ppm/C; EIA_Code: E96; U/M: EA; SizeArea_mm2: 1.28; SizeX_mm: 1.6; SizeY_mm: 0.8; AEC Category: Q200; Green_Lifecycle: Active; Green_REACh: Passed
R37 R55 = CRCW060310K0FKEA: RES, 10.0 k, 1%, 0.1 W, 0603; Manufacturer: Vishay-Dale; CompType: Resistor; Value: 10.0k; Res_ohm: 10000; Value_Code: 10k0; Tolerance_%: 1; Power_W: 0.1; Value2: 0.1W; VDC_V: 75; TempCo: 100 ppm/C; EIA_Code: E96; U/M: EA; SizeArea_mm2: 1.28; SizeX_mm: 1.6; SizeY_mm: 0.8; AEC Category: Q200
R38 R42 R43 R61 R72 = CRCW06030000Z0EA: as R13 on sheet PMP21103_RevB_SH1
R39 = CRCW06034K22FKEA: RES, 4.22 k, 1%, 0.1 W, 0603; Manufacturer: Vishay-Dale; CompType: Resistor; Value: 4.22k; Res_ohm: 4220; Value_Code: 4k22; Tolerance_%: 1; Power_W: 0.1; Value2: 0.1W; VDC_V: 75; TempCo: 100 ppm/C; EIA_Code: E96; U/M: EA; SizeArea_mm2: 1.28; SizeX_mm: 1.6; SizeY_mm: 0.8; AEC Category: Q200; Green_Lifecycle: Active; Green_REACh: Passed
R40 = ERJ-L1DKF10CU: RES, 0.1 ohm, 1%, 0.5W, 2010; Manufacturer: Panasonic; CompType: Resistor; Value_Code: R100; Tolerance_%: 1; Power_W: 0.5; VDC_V: 0; TempCo: 100 ppm/C; EIA_Code: E96; U/M: EA
R44 = CRCW060315K0FKEA: RES, 15.0 k, 1%, 0.1 W, 0603; Manufacturer: Vishay-Dale; CompType: Resistor; Value: 15.0k; Res_ohm: 15000; Value_Code: 15k0; Tolerance_%: 1; Power_W: 0.1; Value2: 0.1W; VDC_V: 75; TempCo: 100 ppm/C; EIA_Code: E96; U/M: EA; SizeArea_mm2: 1.28; SizeX_mm: 1.6; SizeY_mm: 0.8; AEC Category: Q200; Green_Lifecycle: Active; Green_REACh: Passed
R45 = CRCW060321K5FKEA: RES, 21.5 k, 1%, 0.1 W, 0603; Manufacturer: Vishay-Dale; CompType: Resistor; Value: 21.5k; Res_ohm: 21500; Value_Code: 21k5; Tolerance_%: 1; Power_W: 0.1; Value2: 0.1W; VDC_V: 75; TempCo: 100 ppm/C; EIA_Code: E96; U/M: EA; SizeArea_mm2: 1.28; SizeX_mm: 1.6; SizeY_mm: 0.8; AEC Category: Q200; Green_Lifecycle: Active; Green_REACh: Passed
R46 = CRCW060328K7FKEA: RES, 28.7 k, 1%, 0.1 W, 0603; Manufacturer: Vishay-Dale; CompType: Resistor; Value: 28.7k; Res_ohm: 28700; Value_Code: 28k7; Tolerance_%: 1; Power_W: 0.1; Value2: 0.1W; VDC_V: 75; TempCo: 100 ppm/C; SizeArea_mm2: 1.28; SizeX_mm: 1.6; SizeY_mm: 0.8; EIA_Code: E96; U/M: EA; AEC Category: Q200
R47 R51 R52 R57 = CRCW06034K99FKEA: RES, 4.99 k, 1%, 0.1 W, 0603; Manufacturer: Vishay-Dale; CompType: Resistor; Value: 4.99k; Res_ohm: 4990; Value_Code: 4k99; Tolerance_%: 1; Power_W: 0.1; Value2: 0.1W; VDC_V: 75; TempCo: 100 ppm/C; SizeArea_mm2: 1.28; SizeX_mm: 1.6; SizeY_mm: 0.8; EIA_Code: E96; U/M: EA; AEC Category: Q200
R48 R49 = CRCW060310K0FKEA: RES, 10.0 k, 1%, 0.1 W, 0603; Manufacturer: Vishay-Dale; CompType: Resistor; Value: 10.0k; Res_ohm: 10000; Value_Code: 10k0; Tolerance_%: 1; Power_W: 0.1; Value2: 0.1W; VDC_V: 75; TempCo: 100 ppm/C; EIA_Code: E96; U/M: EA; SizeArea_mm2: 1.28; SizeX_mm: 1.6; SizeY_mm: 0.8; AEC Category: Q200; Green_Lifecycle: Active; Green_REACh: Passed
R50 = CRCW06035K90FKEA: RES, 5.90 k, 1%, 0.1 W, 0603; Manufacturer: Vishay-Dale; CompType: Resistor; Value: 5.90k; Res_ohm: 5900; Value_Code: 5k90; Tolerance_%: 1; Power_W: 0.1; Value2: 0.1W; VDC_V: 75; TempCo: 100 ppm/C; EIA_Code: E96; U/M: EA; SizeArea_mm2: 1.28; SizeX_mm: 1.6; SizeY_mm: 0.8; AEC Category: Q200; Green_Lifecycle: Active; Green_REACh: Passed
R53 = CRCW060380K6FKEA: RES, 80.6 k, 1%, 0.1 W, 0603; Manufacturer: Vishay-Dale; CompType: Resistor; Value: 80.6k; Res_ohm: 80600; Value_Code: 80k6; Tolerance_%: 1; Power_W: 0.1; Value2: 0.1W; VDC_V: 75; TempCo: 100 ppm/C; EIA_Code: E96; U/M: EA; SizeArea_mm2: 1.28; SizeX_mm: 1.6; SizeY_mm: 0.8; AEC Category: Q200; Green_Lifecycle: Active; Green_REACh: Passed
R54 R62 = CRCW06032K00FKEA: RES, 2.00 k, 1%, 0.1 W, 0603; Manufacturer: Vishay-Dale; CompType: Resistor; Value: 2.00k; Res_ohm: 2000; Value_Code: 2k00; Tolerance_%: 1; Power_W: 0.1; Value2: 0.1W; VDC_V: 75; TempCo: 100 ppm/C; EIA_Code: E96; U/M: EA; SizeArea_mm2: 1.28; SizeX_mm: 1.6; SizeY_mm: 0.8; AEC Category: Q200; Green_Lifecycle: Active; Green_REACh: Passed
R56 = CRCW060364K9FKEA: RES, 64.9 k, 1%, 0.1 W, 0603; Manufacturer: Vishay-Dale; CompType: Resistor; Value: 64.9k; Res_ohm: 64900; Value_Code: 64k9; Tolerance_%: 1; Power_W: 0.1; Value2: 0.1W; VDC_V: 75; TempCo: 100 ppm/C; EIA_Code: E96; U/M: EA; SizeArea_mm2: 1.28; SizeX_mm: 1.6; SizeY_mm: 0.8; AEC Category: Q200; Green_Lifecycle: Active; Green_REACh: Passed
R58 = CMP-0021990-2: RES, 100 k, 1%, 0.1 W, 0603; Manufacturer: Vishay-Dale; Power_W: 100mW; TempCo: 100 ppm/C; U/M: EA; Value: 100k; EIA_Code: E96; SizeX_mm: 1.6; SizeY_mm: 0.8; SizeZ_mm: 1; Value2: 0.1W; SizeArea_mm2: 1.28; CompType: Resistor; VDC_V: 75V; AEC Category: Q200
R59 = CRCW0603100KFKEA: RES, 100 k, 1%, 0.1 W, 0603; Manufacturer: Vishay-Dale; CompType: Resistor; Value: 100k; Res_ohm: 100000; Tolerance_%: 1; Power_W: 0.1; Value2: 0.1W; VDC_V: 75; TempCo: 100 ppm/C; EIA_Code: E96; U/M: EA; SizeArea_mm2: 1.28; SizeX_mm: 1.6; SizeY_mm: 0.8; AEC Category: Q200; Green_Lifecycle: Active; Green_REACh: Passed
R60 R73 = CRCW06031K00FKEA: RES, 1.00 k, 1%, 0.1 W, 0603; Manufacturer: Vishay-Dale; CompType: Resistor; Value: 1.00k; Res_ohm: 1000; Value_Code: 1k00; Tolerance_%: 1; Power_W: 0.1; Value2: 0.1W; VDC_V: 75; TempCo: 100 ppm/C; EIA_Code: E96; U/M: EA; SizeArea_mm2: 1.28; SizeX_mm: 1.6; SizeY_mm: 0.8; AEC Category: Q200
T2 = CMP-0077243-1: Transformer, 100.5 uH, SMT; Manufacturer: Mentech; SizeAreaWB_mm2: 319.95; SizeArea_mm2: 252.05; AEC Qualified: N; Lp: 100.5; AEC Category: Q200; SizeZ_mm: 12.7; Ind_H: 100.5µH; SizeY_mm: 17.75; Ns1toNp: 0.565; LeakageInd_H: 900nH; Rsec1_ohm: 0.04; DCR_ohm: 1.1d; SizeX_mm: 14.2
U5 = HMHA2801A: as U1 on sheet PMP21103_RevB_SH1
U6 = TL431AIDBVR: Adjustable Precision Shunt Regulator, DBV0005A (SOT-23-5); Alternate Manufacturer: Texas Instruments; Alternate PartNumber: TL431AIDBVT; SymbolCreator: a0411947; CompType: IC; U/M: EA; SizeArea_mm2: 8.12; SizeAreaWB_mm2: 14.82; SizeX_mm: 2.8; SizeY_mm: 2.9; SizeZ_mm: 1.45; Green_Lifecycle: Active; Green_REACh: Passed
U7 = CMP-0031996-2: Advanced Active Clamp PWM Controller with Current Control, -40 to +125 degC, 20-pin QFN (RGP), Green (RoHS & no Sb/Br); Manufacturer: Texas Instruments; Frequency(Max)(kHz): 1000; Regulated Outputs(#): 1; Rating: Catalog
